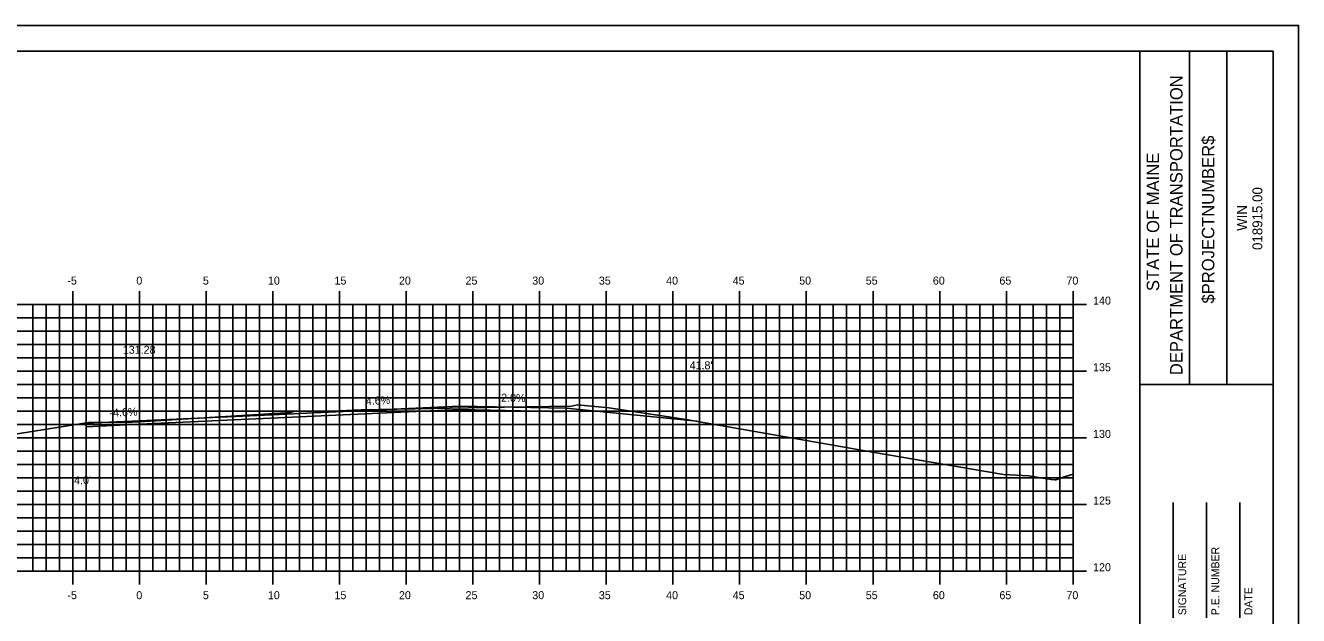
# Model space of a CAD drawing. Extents: x 850630 to 850801, y 365624 to 365734.
# Drawn here: x 850704.2 to 850799.6, y 365689.7 to 365734 of the extents above; entities that cross this region are included whole.
import ezdxf

# ---------------------------------------------------------------- set-up
doc = ezdxf.new("R2010")
doc.units = 0
for name, color, linetype in [('ANNOTATION', 7, 'Continuous'), ('BORDER', 7, 'Continuous'), ('D_Roadway_Centerline', 7, 'Continuous'), ('D_Roadway_Centerline_Text', 7, 'Continuous'), ('D_Roadway_Edge_Shoulder', 7, 'Continuous'), ('D_Roadway_Edge_TW', 7, 'Continuous'), ('D_Roadway_FinishedGrade', 7, 'Continuous'), ('D_Text_Standard', 7, 'Continuous'), ('H_V ANNOTATION', 7, 'Continuous'), ('M_Roadway_Centerline', 7, 'Continuous'), ('MAJOR', 7, 'Continuous'), ('MINOR', 7, 'Continuous'), ('PLOT BOUNDARY', 7, 'Continuous'), ('S_Roadway_Centerline', 7, 'Continuous')]:
    doc.layers.add(name, color=color, linetype=linetype)

msp = doc.modelspace()

# ---------------------------------------------------------------- linework, layer by layer
at = {"layer": 'BORDER'}
for p, q in [((850787.74, 365627.027), (850787.74, 365732.027)), ((850791.468, 365707.024), (850791.468, 365732.024)), ((850794.263, 365707.024), (850794.263, 365732.024)), ((850787.741, 365707.021), (850797.74, 365707.021)), ((850790.24, 365689.53), (850790.24, 365698.177)), ((850792.74, 365689.53), (850792.74, 365698.177)), ((850795.24, 365689.53), (850795.24, 365698.177))]:
    msp.add_line(p, q, dxfattribs=at)
msp.add_lwpolyline([(850637.74, 365627.027), (850797.74, 365627.027), (850797.74, 365732.027), (850637.74, 365732.027)], close=True, dxfattribs=at)
at = {"layer": 'D_Roadway_Centerline'}
msp.add_lwpolyline([(850708.739, 365704.123), (850712.738, 365704.307), (850712.739, 365704.307), (850724.305, 365704.839), (850724.739, 365704.859), (850736.735, 365705.411), (850736.739, 365705.411), (850744.737, 365705.251), (850744.739, 365705.251)], dxfattribs=at)
at = {"layer": 'D_Roadway_Edge_Shoulder'}
for points in [[(850712.739, 365704.049), (850724.739, 365704.601), (850724.739, 365704.859)], [(850724.739, 365704.601), (850736.739, 365705.153), (850736.739, 365705.411)], [(850736.739, 365705.153), (850744.739, 365704.993), (850744.739, 365705.251)], [(850708.737, 365703.865), (850712.739, 365704.049), (850712.739, 365704.307)]]:
    msp.add_lwpolyline(points, dxfattribs=at)
at = {"layer": 'D_Roadway_Edge_TW'}
msp.add_lwpolyline([(850724.739, 365704.859), (850724.739, 365704.692)], dxfattribs=at)
at = {"layer": 'D_Roadway_FinishedGrade'}
msp.add_line((850744.739, 365705.251), (850754.543, 365704.27), dxfattribs=at)
at = {"layer": 'MAJOR'}
for p, q in [((850707.739, 365714.029), (850707.739, 365713.027)), ((850712.739, 365714.029), (850712.739, 365713.027)), ((850717.739, 365714.029), (850717.739, 365713.027)), ((850722.739, 365714.029), (850722.739, 365713.027)), ((850727.739, 365714.029), (850727.739, 365713.027)), ((850732.739, 365714.029), (850732.739, 365713.027)), ((850737.739, 365714.029), (850737.739, 365713.027)), ((850742.739, 365714.029), (850742.739, 365713.027)), ((850747.739, 365714.029), (850747.739, 365713.027)), ((850752.739, 365714.029), (850752.739, 365713.027)), ((850757.739, 365714.029), (850757.739, 365713.027)), ((850762.739, 365714.029), (850762.739, 365713.027)), ((850767.739, 365714.029), (850767.739, 365713.027)), ((850772.739, 365714.029), (850772.739, 365713.027)), ((850777.739, 365714.029), (850777.739, 365713.027)), ((850782.739, 365714.029), (850782.739, 365713.027)), ((850642.739, 365713.027), (850782.739, 365713.027)), ((850642.739, 365713.027), (850782.739, 365713.027)), ((850707.739, 365693.027), (850707.739, 365713.027)), ((850712.739, 365693.027), (850712.739, 365713.027)), ((850717.739, 365693.027), (850717.739, 365713.027)), ((850722.739, 365693.027), (850722.739, 365713.027)), ((850727.739, 365693.027), (850727.739, 365713.027)), ((850732.739, 365693.027), (850732.739, 365713.027)), ((850737.739, 365693.027), (850737.739, 365713.027)), ((850742.739, 365693.027), (850742.739, 365713.027)), ((850747.739, 365693.027), (850747.739, 365713.027)), ((850752.739, 365693.027), (850752.739, 365713.027)), ((850757.739, 365693.027), (850757.739, 365713.027)), ((850762.739, 365693.027), (850762.739, 365713.027)), ((850767.739, 365693.027), (850767.739, 365713.027)), ((850772.739, 365693.027), (850772.739, 365713.027)), ((850777.739, 365693.027), (850777.739, 365713.027)), ((850783.741, 365713.027), (850781.737, 365713.027)), ((850782.739, 365693.027), (850782.739, 365713.027)), ((850782.739, 365693.027), (850782.739, 365713.027)), ((850642.739, 365708.027), (850782.739, 365708.027)), ((850783.741, 365708.027), (850781.737, 365708.027)), ((850642.739, 365703.027), (850782.739, 365703.027)), ((850783.741, 365703.027), (850781.737, 365703.027)), ((850642.739, 365698.027), (850782.739, 365698.027)), ((850783.741, 365698.027), (850781.737, 365698.027)), ((850642.739, 365693.027), (850782.739, 365693.027)), ((850642.739, 365693.027), (850782.739, 365693.027)), ((850707.739, 365692.025), (850707.739, 365693.027)), ((850712.739, 365692.025), (850712.739, 365693.027)), ((850717.739, 365692.025), (850717.739, 365693.027)), ((850722.739, 365692.025), (850722.739, 365693.027)), ((850727.739, 365692.025), (850727.739, 365693.027)), ((850732.739, 365692.025), (850732.739, 365693.027)), ((850737.739, 365692.025), (850737.739, 365693.027)), ((850742.739, 365692.025), (850742.739, 365693.027)), ((850747.739, 365692.025), (850747.739, 365693.027)), ((850752.739, 365692.025), (850752.739, 365693.027)), ((850757.739, 365692.025), (850757.739, 365693.027)), ((850762.739, 365692.025), (850762.739, 365693.027)), ((850767.739, 365692.025), (850767.739, 365693.027)), ((850772.739, 365692.025), (850772.739, 365693.027)), ((850777.739, 365692.025), (850777.739, 365693.027)), ((850783.741, 365693.027), (850781.737, 365693.027)), ((850782.739, 365692.025), (850782.739, 365693.027))]:
    msp.add_line(p, q, dxfattribs=at)
at = {"layer": 'MINOR'}
for p, q in [((850704.739, 365693.027), (850704.739, 365713.027)), ((850705.739, 365693.027), (850705.739, 365713.027)), ((850706.739, 365693.027), (850706.739, 365713.027)), ((850708.739, 365693.027), (850708.739, 365713.027)), ((850709.739, 365693.027), (850709.739, 365713.027)), ((850710.739, 365693.027), (850710.739, 365713.027)), ((850711.739, 365693.027), (850711.739, 365713.027)), ((850713.739, 365693.027), (850713.739, 365713.027)), ((850714.739, 365693.027), (850714.739, 365713.027)), ((850715.739, 365693.027), (850715.739, 365713.027)), ((850716.739, 365693.027), (850716.739, 365713.027)), ((850718.739, 365693.027), (850718.739, 365713.027)), ((850719.739, 365693.027), (850719.739, 365713.027)), ((850720.739, 365693.027), (850720.739, 365713.027)), ((850721.739, 365693.027), (850721.739, 365713.027)), ((850723.739, 365693.027), (850723.739, 365713.027)), ((850724.739, 365693.027), (850724.739, 365713.027)), ((850725.739, 365693.027), (850725.739, 365713.027)), ((850726.739, 365693.027), (850726.739, 365713.027)), ((850728.739, 365693.027), (850728.739, 365713.027)), ((850729.739, 365693.027), (850729.739, 365713.027)), ((850730.739, 365693.027), (850730.739, 365713.027)), ((850731.739, 365693.027), (850731.739, 365713.027)), ((850733.739, 365693.027), (850733.739, 365713.027)), ((850734.739, 365693.027), (850734.739, 365713.027)), ((850735.739, 365693.027), (850735.739, 365713.027)), ((850736.739, 365693.027), (850736.739, 365713.027)), ((850738.739, 365693.027), (850738.739, 365713.027)), ((850739.739, 365693.027), (850739.739, 365713.027)), ((850740.739, 365693.027), (850740.739, 365713.027)), ((850741.739, 365693.027), (850741.739, 365713.027)), ((850743.739, 365693.027), (850743.739, 365713.027)), ((850744.739, 365693.027), (850744.739, 365713.027)), ((850745.739, 365693.027), (850745.739, 365713.027)), ((850746.739, 365693.027), (850746.739, 365713.027)), ((850748.739, 365693.027), (850748.739, 365713.027)), ((850749.739, 365693.027), (850749.739, 365713.027)), ((850750.739, 365693.027), (850750.739, 365713.027)), ((850751.739, 365693.027), (850751.739, 365713.027)), ((850753.739, 365693.027), (850753.739, 365713.027)), ((850754.739, 365693.027), (850754.739, 365713.027)), ((850755.739, 365693.027), (850755.739, 365713.027)), ((850756.739, 365693.027), (850756.739, 365713.027)), ((850758.739, 365693.027), (850758.739, 365713.027)), ((850759.739, 365693.027), (850759.739, 365713.027)), ((850760.739, 365693.027), (850760.739, 365713.027)), ((850761.739, 365693.027), (850761.739, 365713.027)), ((850763.739, 365693.027), (850763.739, 365713.027)), ((850764.739, 365693.027), (850764.739, 365713.027)), ((850765.739, 365693.027), (850765.739, 365713.027)), ((850766.739, 365693.027), (850766.739, 365713.027)), ((850768.739, 365693.027), (850768.739, 365713.027)), ((850769.739, 365693.027), (850769.739, 365713.027)), ((850770.739, 365693.027), (850770.739, 365713.027)), ((850771.739, 365693.027), (850771.739, 365713.027)), ((850773.739, 365693.027), (850773.739, 365713.027)), ((850774.739, 365693.027), (850774.739, 365713.027)), ((850775.739, 365693.027), (850775.739, 365713.027)), ((850776.739, 365693.027), (850776.739, 365713.027)), ((850778.739, 365693.027), (850778.739, 365713.027)), ((850779.739, 365693.027), (850779.739, 365713.027)), ((850780.739, 365693.027), (850780.739, 365713.027)), ((850781.739, 365693.027), (850781.739, 365713.027)), ((850642.739, 365712.027), (850782.739, 365712.027)), ((850782.739, 365712.027), (850781.737, 365712.027)), ((850642.739, 365711.027), (850782.739, 365711.027)), ((850782.739, 365711.027), (850781.737, 365711.027)), ((850642.739, 365710.027), (850782.739, 365710.027)), ((850782.739, 365710.027), (850781.737, 365710.027)), ((850642.739, 365709.027), (850782.739, 365709.027)), ((850782.739, 365709.027), (850781.737, 365709.027)), ((850642.739, 365707.027), (850782.739, 365707.027)), ((850782.739, 365707.027), (850781.737, 365707.027)), ((850642.739, 365706.027), (850782.739, 365706.027)), ((850782.739, 365706.027), (850781.737, 365706.027)), ((850642.739, 365705.027), (850782.739, 365705.027)), ((850782.739, 365705.027), (850781.737, 365705.027)), ((850642.739, 365704.027), (850782.739, 365704.027)), ((850782.739, 365704.027), (850781.737, 365704.027)), ((850642.739, 365702.027), (850782.739, 365702.027)), ((850782.739, 365702.027), (850781.737, 365702.027)), ((850642.739, 365701.027), (850782.739, 365701.027)), ((850782.739, 365701.027), (850781.737, 365701.027)), ((850642.739, 365700.027), (850782.739, 365700.027)), ((850782.739, 365700.027), (850781.737, 365700.027)), ((850642.739, 365699.027), (850782.739, 365699.027)), ((850782.739, 365699.027), (850781.737, 365699.027)), ((850642.739, 365697.027), (850782.739, 365697.027)), ((850782.739, 365697.027), (850781.737, 365697.027)), ((850642.739, 365696.027), (850782.739, 365696.027)), ((850782.739, 365696.027), (850781.737, 365696.027)), ((850642.739, 365695.027), (850782.739, 365695.027)), ((850782.739, 365695.027), (850781.737, 365695.027)), ((850642.739, 365694.027), (850782.739, 365694.027)), ((850782.739, 365694.027), (850781.737, 365694.027))]:
    msp.add_line(p, q, dxfattribs=at)
at = {"layer": 'PLOT BOUNDARY'}
msp.add_lwpolyline([(850629.646, 365623.968), (850799.646, 365623.968), (850799.646, 365733.968), (850629.646, 365733.968)], close=True, dxfattribs=at)
at = {"layer": 'S_Roadway_Centerline'}
msp.add_lwpolyline([(850699.934, 365702.767), (850708.915, 365704.192), (850712.193, 365704.212), (850712.741, 365704.233), (850724.058, 365704.923), (850724.376, 365705.022), (850727.724, 365705.064), (850729.361, 365705.123), (850740.07, 365705.344), (850745.12, 365705.411), (850745.588, 365705.503), (850747.939, 365705.285), (850753.718, 365704.397), (850764.886, 365702.455), (850767.7, 365701.952), (850777.535, 365700.291), (850779.414, 365700.17), (850781.101, 365699.906), (850781.362, 365699.875), (850781.442, 365699.878), (850782.184, 365700.124), (850782.739, 365700.306)], dxfattribs=at)

# ---------------------------------------------------------------- texts
at = {"layer": 'ANNOTATION'}
for s, rotation, p in [('4.6%', 2.63371, (850729.718, 365705.489)), ('-2.0%', 358.8542, (850739.582, 365705.754)), ('-4.6%', 2.6341, (850710.499, 365704.605))]:
    msp.add_text(s, height=0.6, rotation=rotation, dxfattribs=at).set_placement(p)
at = {"layer": 'BORDER'}
for s, height, p in [('DEPARTMENT OF TRANSPORTATION', 0.93176, (850790.946, 365707.733)), ('$PROJECTNUMBER$', 0.93176, (850793.332, 365713.106)), ('STATE OF MAINE', 0.93176, (850789.195, 365714.039)), ('018915.00', 0.7453, (850796.935, 365717.125)), ('WIN', 0.7453, (850795.776, 365718.557)), ('SIGNATURE', 0.5906, (850791.22, 365689.722)), ('P.E. NUMBER', 0.59055, (850793.7, 365689.722)), ('DATE', 0.5906, (850796.181, 365689.722))]:
    msp.add_text(s, height=height, rotation=90, dxfattribs=at).set_placement(p)
at = {"layer": 'D_Roadway_Centerline'}
for s, p in [('C', (850712.734, 365704.307)), ('L', (850712.739, 365704.299))]:
    msp.add_text(s, height=0.0146, dxfattribs=at).set_placement(p)
at = {"layer": 'D_Roadway_Centerline_Text'}
msp.add_text('131.28', height=0.6, dxfattribs=at).set_placement((850711.485, 365709.339))
at = {"layer": 'D_Text_Standard'}
for s, p in [("41.8'", (850753.987, 365708.169)), ("4.0'", (850707.831, 365699.553))]:
    msp.add_text(s, height=0.6, dxfattribs=at).set_placement(p)
at = {"layer": 'H_V ANNOTATION'}
for s, p in [('-5', (850707.33, 365714.527)), ('0', (850712.499, 365714.527)), ('5', (850717.491, 365714.527)), ('10', (850722.365, 365714.527)), ('15', (850727.357, 365714.527)), ('20', (850732.193, 365714.527)), ('25', (850737.185, 365714.527)), ('30', (850742.188, 365714.527)), ('35', (850747.18, 365714.527)), ('40', (850752.226, 365714.527)), ('45', (850757.218, 365714.527)), ('50', (850762.204, 365714.527)), ('55', (850767.196, 365714.527)), ('60', (850772.226, 365714.527)), ('65', (850777.218, 365714.527)), ('70', (850782.242, 365714.527)), ('140', (850784.239, 365713.027)), ('135', (850784.239, 365708.027)), ('130', (850784.239, 365703.027)), ('125', (850784.239, 365698.027)), ('120', (850784.239, 365693.027)), ('-5', (850707.33, 365690.927)), ('0', (850712.499, 365690.927)), ('5', (850717.491, 365690.927)), ('10', (850722.365, 365690.927)), ('15', (850727.357, 365690.927)), ('20', (850732.193, 365690.927)), ('25', (850737.185, 365690.927)), ('30', (850742.188, 365690.927)), ('35', (850747.18, 365690.927)), ('40', (850752.226, 365690.927)), ('45', (850757.218, 365690.927)), ('50', (850762.204, 365690.927)), ('55', (850767.196, 365690.927)), ('60', (850772.226, 365690.927)), ('65', (850777.218, 365690.927)), ('70', (850782.242, 365690.927))]:
    msp.add_text(s, height=0.6, dxfattribs=at).set_placement(p)
at = {"layer": 'M_Roadway_Centerline'}
for s, p in [('C', (850724.371, 365705.022)), ('L', (850724.376, 365705.015))]:
    msp.add_text(s, height=0.0146, dxfattribs=at).set_placement(p)

doc.saveas('drawing.dxf')
